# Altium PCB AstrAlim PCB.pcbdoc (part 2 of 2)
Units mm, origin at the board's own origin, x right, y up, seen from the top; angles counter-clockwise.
Board outline 112.02 x 78.49 mm, 4 copper layers (Top Layer, Inner1, Inner2, Bottom Layer); 151 components, 74 nets, 446 pads, 97 vias.
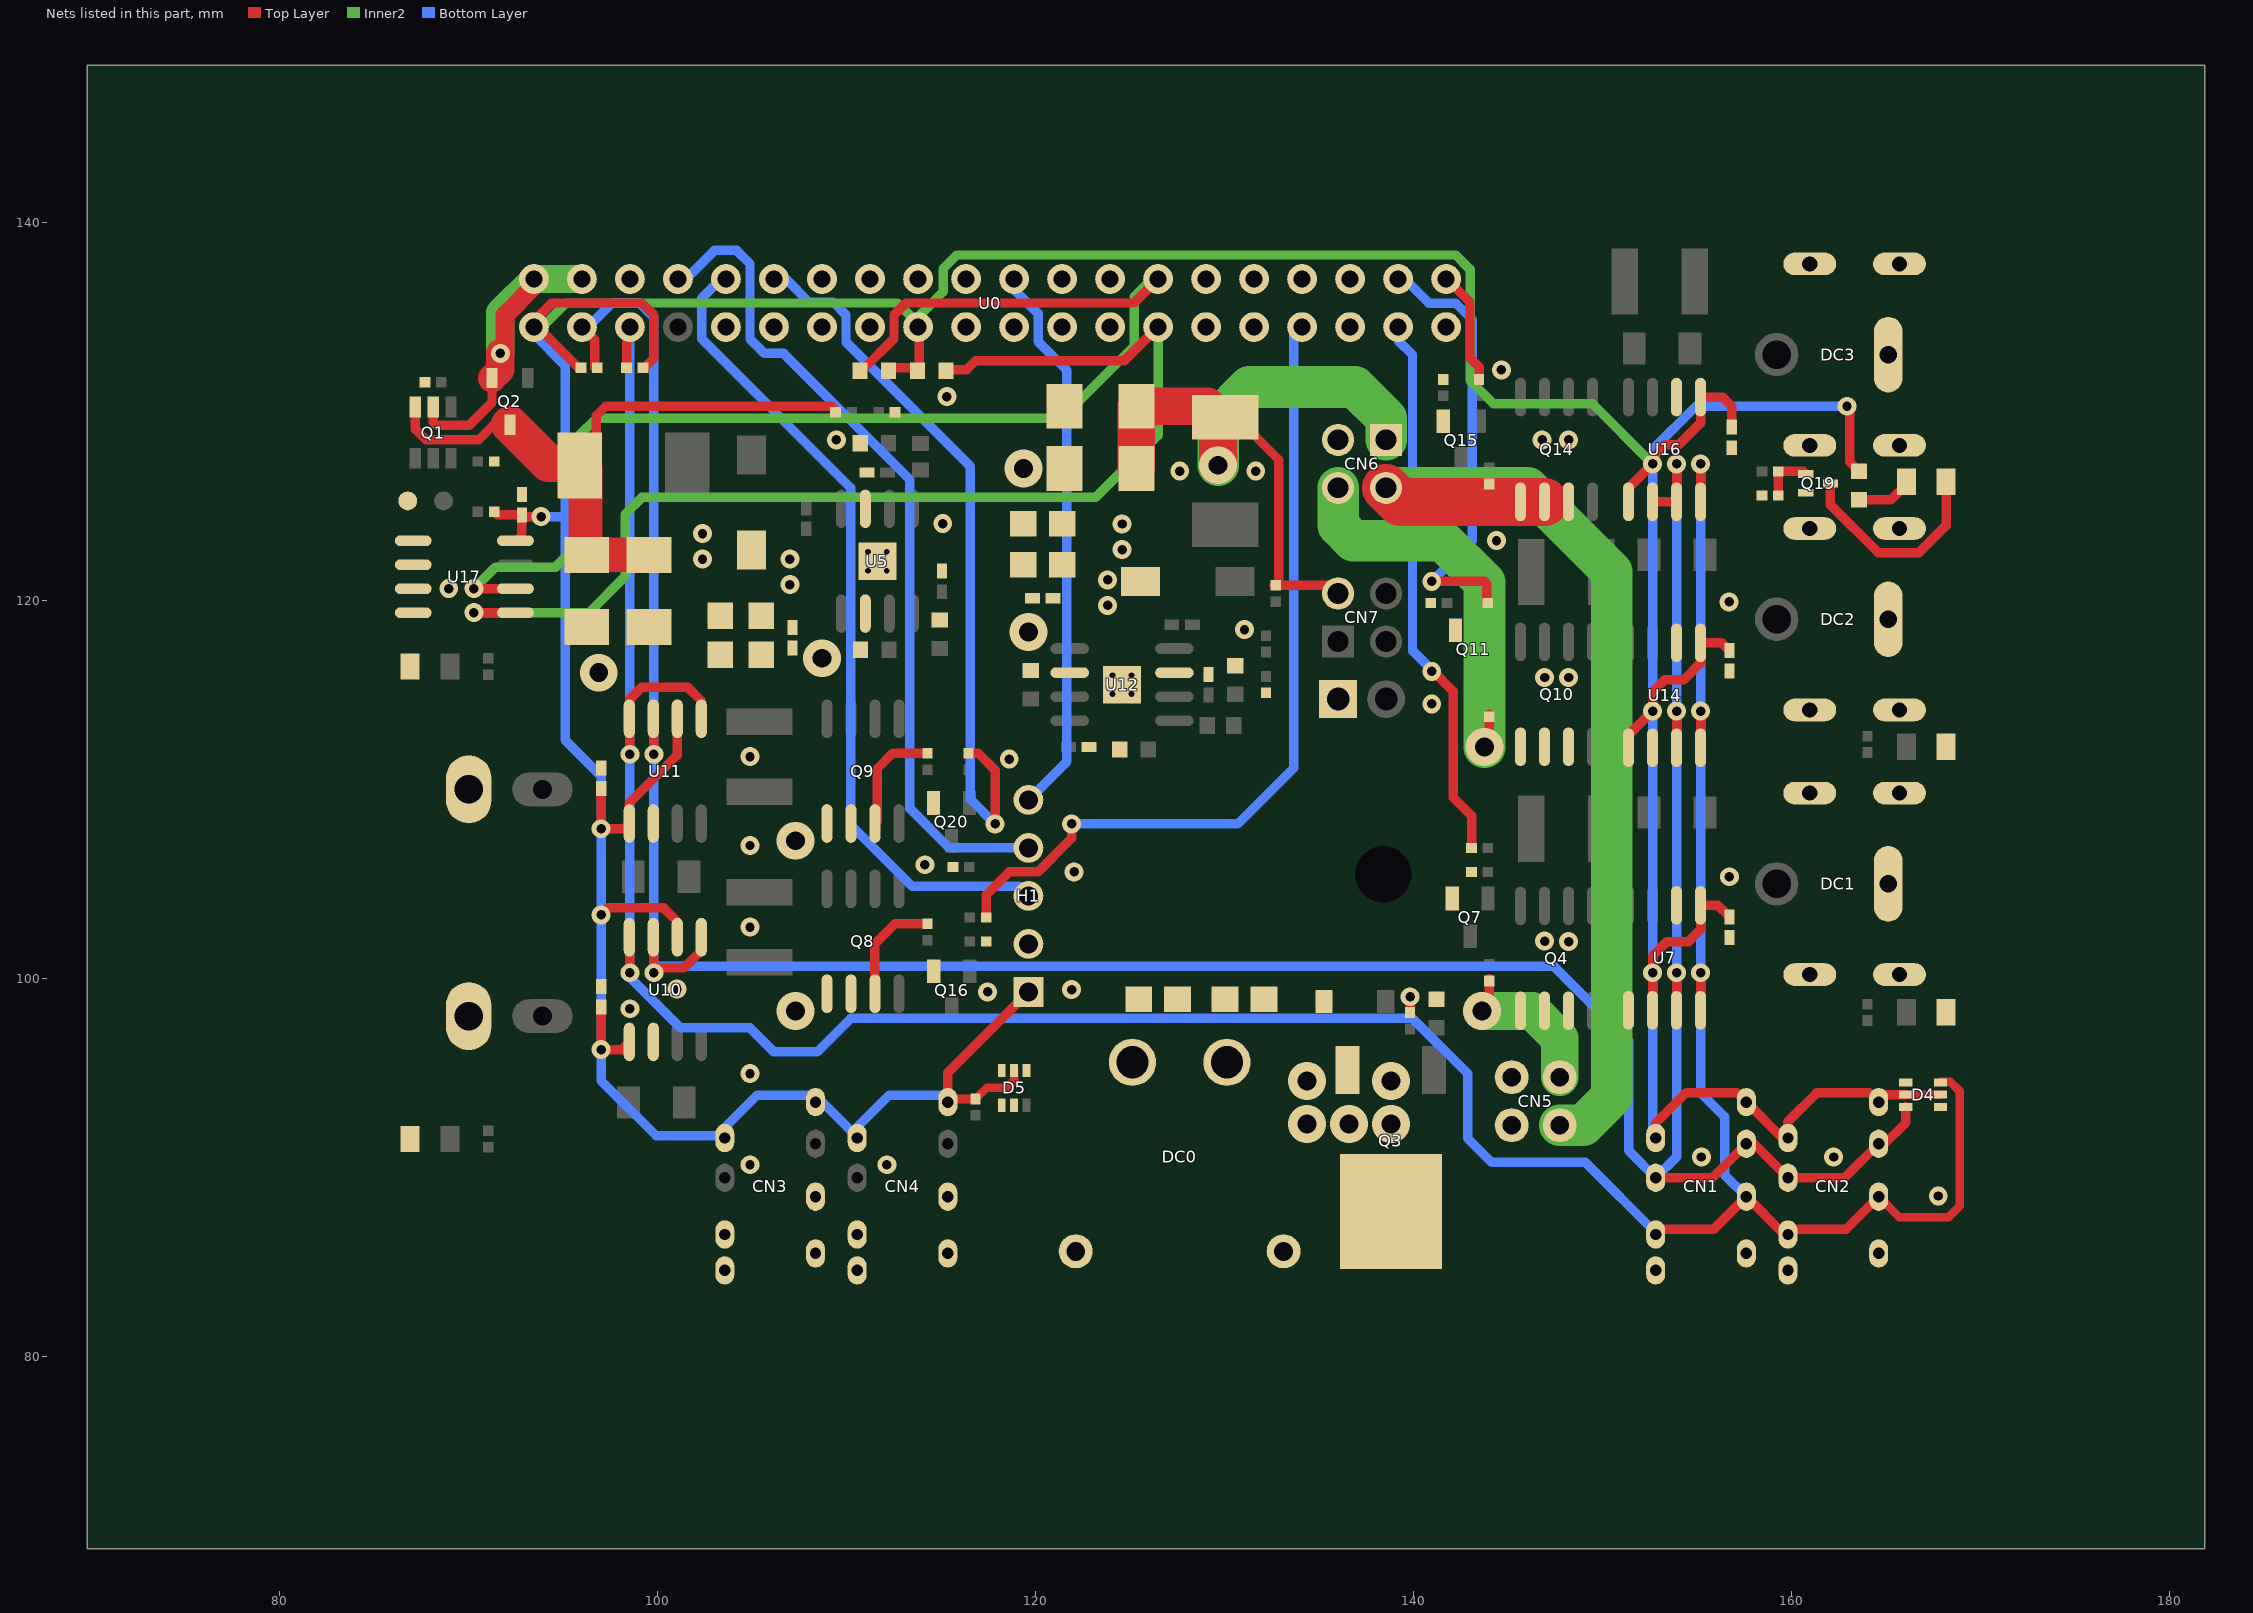
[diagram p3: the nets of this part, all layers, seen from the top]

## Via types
v1: diameter 1, hole 0.5, Top Layer to Bottom Layer, 69 vias
v2: diameter 2, hole 1, Top Layer to Bottom Layer, 14 vias
v3: diameter 0.61, hole 0.305, Top Layer to Bottom Layer, 8 vias
v4: diameter 0.8, hole 0.4, Top Layer to Bottom Layer, 6 vias

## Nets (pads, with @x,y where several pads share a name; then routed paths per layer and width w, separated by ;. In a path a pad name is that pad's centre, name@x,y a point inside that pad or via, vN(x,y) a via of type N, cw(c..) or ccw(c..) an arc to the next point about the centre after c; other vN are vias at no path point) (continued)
$2N49861: Q19.1 R86.1 R87.2 | length 2.8
  Top Layer w0.5: R87.2@159.315,125.586 R86.1@159.315,126.856 160.631,126.856 Q19.1@160.772,126.715
$2N50059: LED13.2 Q19.3 | length 11.1
  Top Layer w0.5: Q19.3@162.072,126.215 162.072,125.08 164.597,122.555 166.756,122.555 168.187,123.986 LED13.2@168.187,126.176
$2N57491: LED13.1 R88.2 | length 2.8
  Top Layer w0.5: R88.2@163.581,125.358 165.268,125.358 LED13.1@166.087,126.176
+3.3V: C16.1 C19.1 C20.1 C30.1 C32.1 C38.2 CN1.4 CN1.8 CN2.4 CN2.8 CN3.4 CN3.8 CN4.4 CN4.8 D4.2 D4.5 D5.5 H1.1 R6.2 R7.2 R19.2 R88.1 R89.2 R90.2 R91.2 U0.1 U0.17 U7.2 U7.5 U10.2 U10.5 U11.2 U11.5 U14.1 U14.5 U16.1 U16.5 U17.8 | length 288.9
  Top Layer w0.45: R19.2@116.845,93.651 117.428,94.234 118.496,94.234 118.877,94.615 D5.5@118.877,95.154 ; D4.5@166.051,93.881 D4.2@167.891,93.881
  Top Layer w0.5: R91.2@91.37,124.714 91.534,124.55 C38.2@92.842,124.55 ; U17.8@92.245,123.19 92.588,123.19 92.842,123.444 C38.2@92.842,124.55 ; v1(93.858,124.46) 92.932,124.46 C38.2@92.842,124.55 ; R6.2@95.838,132.334 93.679,134.493 U0.1@93.477,134.493 93.477,134.813 94.427,135.763 99.184,135.763 99.827,135.12 99.827,132.842 99.319,132.334 R7.2@99.244,132.334 ; C19.1@97.033,98.515 v1(97.033,96.266) 98.119,96.266 U10.5@98.521,96.669 ; v1(97.033,103.394) 97.398,103.759 100.335,103.759 101.061,103.032 U10.2@101.061,102.213 ; C20.1@97.033,110.072 v1(97.033,107.95) 98.246,107.95 U11.5@98.521,108.225 98.521,109.305 101.061,111.845 U11.2@101.061,113.77 ; R90.2@112.579,132.334 113.872,132.334 113.872,134.418 U0.17@113.797,134.493 ; CN4.4@115.418,93.651 CN4.4@115.545,93.651 ; R19.2@116.845,93.651 CN4.4@115.545,93.651 ; H1.1@119.639,99.314 115.377,95.052 CN4.4@115.377,93.483 CN4.4@115.545,93.651 ; U14.1@151.389,112.232 151.389,112.903 v1(152.659,114.173) 152.659,115.189 153.294,115.824 154.31,115.824 155.199,116.713 U14.5@155.199,117.777 156.331,117.777 C30.1@156.723,117.385 ; U16.1@151.389,125.244 151.389,125.984 v1(152.659,127.254) 152.659,127.58 153.349,128.27 154.056,128.27 155.199,129.413 U16.5@155.199,130.788 156.364,130.788 156.85,130.302 C32.1@156.85,129.196 ; U7.2@152.659,98.347 v1(152.659,100.33) 152.659,101.219 153.421,101.981 154.564,101.981 155.199,102.616 U7.5@155.199,103.891 156.12,103.891 C16.1@156.723,103.288 ; CN1.8@152.823,91.583 152.823,92.366 154.437,93.98 157.126,93.98 CN1.4@157.623,93.483 159.523,91.583 CN2.8@159.823,91.583 159.823,92.453 161.353,93.983 164.123,93.983 CN2.4@164.623,93.483 165.021,93.881 D4.5@166.051,93.881 ; v1(162.946,130.302) 163.081,130.167 163.081,127.364 R88.1@163.581,126.864
  Inner2 w0.5: U0.1@93.477,134.493 93.92,134.493 95.19,135.763 112.707,135.763 U0.17@113.797,134.673 ; U0.17@113.797,134.493 U0.17@113.797,134.673 ; v1(152.659,127.254) 149.484,130.429 144.248,130.429 143.007,131.67 143.007,137.541 142.245,138.303 115.85,138.303 115.133,137.586 115.133,136.365 113.797,135.03 U0.17@113.797,134.673
  Bottom Layer w0.5: U0.1@93.477,134.493 93.477,134.116 95.128,132.465 95.128,124.48 ; v1(93.858,124.46) 95.108,124.46 95.128,124.48 ; CN4.4@115.308,93.604 115.059,93.853 112.273,93.853 110.316,91.896 108.359,93.853 105.288,93.853 103.523,92.088 103.523,91.704 99.944,91.704 97.033,94.615 v1(97.033,96.266) v1(97.033,103.394) v1(97.033,107.95) 97.033,110.744 95.128,112.649 95.128,124.48 ; CN1.8@153.077,91.583 152.659,92.001 v1(152.659,100.33) v1(152.659,114.173) v1(152.659,127.254) 152.659,128.004 154.957,130.302 v1(162.946,130.302)
+5V_A: C10.1 C11.1 Q1.6 Q2.3 R14.2 U6.2 | length 34.4
  Top Layer w0.5: Q1.6@87.193,130.255 87.193,129.093 87.762,128.524 90.556,128.524 91.353,129.321 Q2.3@92.207,129.321 ; U6.2@95.89,127.285 96.779,128.174 96.779,129.802 97.279,130.302 109.237,130.302 109.427,130.112 R14.2@109.427,129.984
  Top Layer w1.8: U6.2@95.89,127.285 96.2,126.975 96.2,122.473 96.229,122.444 C11.1@98.482,122.444
  Top Layer w2: Q2.3@92.207,129.321 94.243,127.285 U6.2@95.89,127.285
+5V_PI: Q1.5 Q2.2 U0.2 U0.4 | length 19.2
  Top Layer w0.5: Q1.5@88.143,130.255 88.143,129.451 88.308,129.286 90.048,129.286 91.257,130.495 Q2.2@91.257,131.791
  Top Layer w1: v1(91.699,133.096) 91.953,133.35 91.953,135.128 93.477,136.652 U0.2@93.477,137.033
  Top Layer w1.5: Q2.2@91.257,131.791 91.699,132.233 v1(91.699,133.096)
  Inner2 w1.5: v1(91.699,133.096) 91.699,135.255 U0.2@93.477,137.033 U0.4@96.017,137.033
+9V: C26.1 C27.1 CN6.1 CN7.2 R67.2 U13.2 | length 38.7
  Top Layer w0.5: U13.2@129.672,129.723 130.632,129.723 132.887,127.468 132.887,121.071 132.645,120.829 135.589,120.829 CN7.2@136.022,120.396
  Top Layer w2: C27.1@125.348,127 C26.1@125.348,130.302 129.093,130.302 129.672,129.723 v2(129.672,127.182)
  Inner2 w2.2: v2(129.672,127.182) 129.672,129.667 131.323,131.318 136.911,131.318 138.562,129.667 CN6.1@138.562,128.524
+12V: C5.2 C6.2 C7.2 C21.2 C22.2 C23.2 C34.2 C35.2 CN5.2 CN6.4 DC0.2 Q4.1 Q4.2 Q4.3 Q8.1 Q8.2 Q8.3 Q9.1 Q9.2 Q9.3 Q10.1 Q10.2 Q10.3 R10.2 R17.1 R22.2 R27.2 R30.2 R32.2 R42.2 U5.2 U12.2 | length 42.8
  Top Layer w0.5: Q8.3@111.518,99.219 111.511,99.227 111.511,101.854 112.579,102.922 R27.2@114.305,102.922 ; Q9.3@111.518,108.225 111.638,108.345 111.638,111.125 112.452,111.939 R30.2@114.305,111.939 ; R17.1@139.832,98.223 v1(139.832,99.06) ; v2(143.642,98.298) 144.023,98.679 R22.2@144.023,100.024 ; v2(143.769,112.268) 144.023,112.522 R42.2@144.023,113.994
  Inner2 w2: v2(143.642,98.298) 146.309,98.298 147.747,96.86 CN5.2@147.747,94.803
  Inner2 w2.2: CN6.4@136.022,125.984 136.022,123.993 136.825,123.19 141.569,123.19 143.769,120.99 v2(143.769,112.268)
  other v2: 107.32,98.298 107.32,107.315 108.717,116.967 119.639,118.364
GND: AV0.1 AV1.1 C5.1 C6.1 C7.1 C8.1 C10.2 C11.2 C13.1 C16.2 C19.2 C20.2 C21.1 C22.1 C23.1 C24.1 C26.2 C27.2 C29.1 C30.2 C32.2 C34.1 C35.1 C38.1 CN1.1 CN1.5 CN2.1 CN2.5 CN3.1 CN3.5 CN4.1 CN4.5 CN5.1 CN5.3 CN8.1 D1.1 D2.2 D3.1 D4.1 D4.4 D5.4 DC1.2 DC1.3 DC2.2 DC2.3 DC3.2 DC3.3 GN0.1 H1.2 LED1.2 LED2.2 LED4.2 LED5.2 pad.41 Q3.3 Q7.2 Q11.2 Q15.2 Q16.2 Q19.2 Q20.2 R11.1 R12.2 R13.1 R16.1 R18.1 R20.1 R33.1 R34.2 R39.1 R40.1 R48.1 R54.1 R56.1 R59.1 R87.1 U0.6 U0.9 U0.14 U0.20 U0.25 U0.30 U0.34 U0.39 U5.7 U5.9 U7.1 U7.6 U10.6 U11.6 U12.7 U12.9 U14.2 U14.6 U16.6 U17.3 U17.4
  other v1: 167.772,88.519 104.907,90.17 112.146,90.17 155.242,90.581 162.242,90.581 104.907,94.996 98.557,98.425 117.48,99.314 121.925,99.441 101.044,99.462 148.214,101.981 146.944,102 104.907,102.743 156.723,105.41 122.052,105.664 114.164,106.045 104.907,107.061 118.623,111.633 104.907,111.76 140.975,114.554 146.944,115.951 148.214,115.951 131.069,118.481 123.83,119.761 156.713,119.955 88.969,120.65 107.021,120.863 123.83,121.113 102.396,122.215 107.021,122.215 124.592,122.719 144.404,123.19 102.396,123.565 124.592,124.071 115.104,124.095 127.643,126.873 131.664,126.873 109.479,128.524 146.817,128.524 148.214,128.524 115.321,130.81 144.658,132.222
  other v2: 134.371,92.329 136.593,92.329 138.816,92.329 134.371,94.605 138.816,94.605 96.906,116.205 119.385,127
GND_IN: DC0.1 Q3.2
GPIO13_PWM1: R53.1 U0.33 | length 44.2
  Top Layer w0.5: R53.1@117.405,103.251 117.405,104.446 118.623,105.664 120.147,105.664 121.925,107.442 v1(121.925,108.204)
  Bottom Layer w0.5: v1(121.925,108.204) 130.715,108.204 133.672,111.161 133.672,133.99 U0.33@134.128,134.447
GPIO18_PWM0: R55.1 U0.12 | length 39.4
  Top Layer w0.5: R55.1@116.464,111.939 116.984,111.939 117.873,111.05 v1(117.873,108.204)
  Bottom Layer w0.5: U0.12@106.177,137.033 106.804,137.033 108.035,135.802 109.313,135.802 109.987,135.128 109.987,133.698 116.566,127.119 116.566,109.511 v1(117.873,108.204)
GPIO20: R41.1 U0.38 | length 23.5
  Top Layer w0.5: v1(140.975,121.031) 143.769,121.031 143.896,120.904 143.896,119.94 R41.1@143.948,119.888
  Bottom Layer w0.5: U0.38@139.22,136.951 139.63,136.951 140.829,135.752 142.245,135.752 143.117,134.881 143.117,123.173 v1(140.975,121.031)
GPIO21: R49.1 U0.40 | length 6
  Top Layer w0.5: U0.40@141.794,137.013 143,135.807 143,132.855 143.495,132.361 R49.1@143.495,131.727
GPIO26: R21.1 U0.37 | length 29.2
  Top Layer w0.5: v1@141.064,116.269 142.118,115.215 142.118,109.601 143.092,108.627 143.082,108.617 R21.1@143.082,106.934
  Bottom Layer w0.5: U0.37@139.197,134.493 139.197,133.786 139.959,133.024 139.959,117.374 v1@141.064,116.269
  other v1: 140.975,116.269
ID_SC: R90.1 U0.28 U17.6 | length 68.3
  Top Layer w0.5: v1(90.302,120.65) U17.6@92.245,120.65 ; R90.1@110.732,132.285 110.922,132.285 112.527,133.89 112.527,135.128 113.162,135.763 125.227,135.763 U0.28@126.497,137.033
  Inner2 w0.5: v1(90.302,120.65) 91.445,121.793 94.62,121.793 95.89,123.063 95.89,128.778 96.779,129.667 121.417,129.667 125.227,133.477 125.227,136.095 126.165,137.033 U0.28@126.497,137.033
ID_SD: R89.1 U0.27 U17.5 | length 61.8
  Top Layer w0.5: v1(90.302,119.38) U17.5@92.245,119.38 ; R89.1@115.331,132.231 116.369,132.231 116.852,132.715 ; 116.856,132.719 116.852,132.715 ; U0.27@126.497,134.493 124.719,132.715 116.852,132.715
  Inner2 w0.5: v1(90.302,119.38) 96.398,119.38 98.303,121.285 98.303,124.587 99.192,125.476 123.195,125.476 126.497,128.778 U0.27@126.497,134.493
PPS: H1.5 U0.22 | length 29.6
  Bottom Layer w0.5: U0.22@118.877,137.033 118.877,136.479 120.147,135.209 120.147,133.731 121.671,132.207 121.671,111.506 H1.5@119.639,109.474
RXD: H1.3 U0.10 | length 43.8
  Bottom Layer w0.5: U0.10@103.637,137.033 103.375,137.033 102.367,136.025 102.367,133.858 110.241,125.984 110.241,108.142 113.489,104.894 119.139,104.894 H1.3@119.639,104.394
SCL: CN1.2 CN1.6 CN2.2 CN2.6 D4.3 R7.1 U0.5 U7.4 U10.4 U11.1 U11.4 U14.4 U16.4 | length 182.6
  Top Layer w0.45: CN2.2@164.623,88.483 165.723,87.383 168.304,87.383 168.915,87.994 168.915,94.058 168.415,94.558 D4.3@167.917,94.558
  Top Layer w0.5: R7.1@98.378,132.334 98.378,134.314 U0.5@98.557,134.493 ; U10.4@98.521,102.213 98.557,102.178 v1(98.557,100.33) ; U11.4@98.521,113.77 U11.4@98.557,113.735 ; v1(98.557,111.887) U11.4@98.557,113.735 ; U11.1@102.331,113.77 102.331,114.716 101.605,115.443 99.192,115.443 98.557,114.808 U11.4@98.557,113.735 ; CN1.6@152.823,86.483 153.107,86.767 155.907,86.767 CN1.2@157.623,88.483 159.623,86.483 CN2.6@159.823,86.483 160.107,86.767 162.907,86.767 CN2.2@164.623,88.483 ; U7.4@155.199,98.347 v1(155.199,100.33) ; U14.4@155.199,112.232 v1(155.199,114.173) ; U16.4@155.199,125.244 v1(155.199,127.254)
  Bottom Layer w0.5: U0.5@98.557,134.493 v1(98.557,111.887) v1(98.557,100.33) 98.557,100.076 101.224,97.409 104.907,97.409 106.177,96.139 108.463,96.139 110.241,97.917 139.959,97.917 142.88,94.996 142.88,91.567 144.15,90.297 149.103,90.297 CN1.6@152.854,86.546 ; CN1.6@152.663,86.483 CN1.6@152.823,86.483 ; v1(155.199,127.254) v1(155.199,114.173) v1(155.199,100.33) 155.199,93.98 156.469,92.71 156.469,89.637 CN1.2@157.623,88.483
SDA: CN1.3 CN1.7 CN2.3 CN2.7 D4.6 R6.1 U0.3 U7.3 U10.1 U10.3 U11.3 U14.3 U16.2 U16.3 | length 172.4
  Top Layer w0.5: U0.3@96.017,134.493 96.704,133.806 R6.1@96.704,132.334 ; U10.3@99.791,102.213 99.827,102.178 v1(99.827,100.33) 100.081,100.584 101.409,100.584 102.331,101.506 U10.1@102.331,102.213 ; U11.3@99.791,113.77 99.827,113.735 v1(99.827,111.887) ; U16.2@152.659,125.244 U16.3@153.929,125.244 v1(153.929,127.254) ; CN1.7@152.823,89.483 155.823,89.483 CN1.3@157.623,91.283 ; U7.3@153.929,98.347 v1(153.929,100.33) ; U14.3@153.929,112.232 v1(153.929,114.173) ; CN1.3@157.877,91.283 158.023,91.283 CN2.7@159.823,89.483 162.823,89.483 CN2.3@164.623,91.283 164.948,91.283 166.051,92.386 D4.6@166.051,93.231
  Bottom Layer w0.5: U0.3@96.017,134.493 96.329,134.493 97.599,135.763 99.065,135.763 99.827,135.001 v1(99.827,111.887) v1(99.827,100.33) 100.161,100.664 147.45,100.664 151.389,96.726 151.389,90.917 152.823,89.483 153.929,90.589 v1(153.929,100.33) v1(153.929,114.173) v1(153.929,127.254)
TXD: H1.4 U0.8 | length 44.8
  Bottom Layer w0.5: U0.8@101.097,137.033 101.515,137.033 103.028,138.546 104.199,138.546 104.907,137.839 104.907,133.858 105.669,133.096 106.685,133.096 113.367,126.414 113.367,109.015 115.448,106.934 H1.4@119.639,106.934
VS: CN5.4 CN6.2 Q14.1 Q14.2 Q14.3 R50.2 | length 53.6
  Top Layer w2.54: CN6.2@138.562,125.984 139.324,125.222 146.922,125.222 Q14.2@146.944,125.244
  Inner2 w2.2: CN6.2@138.562,125.984 146.055,125.984 150.5,121.539 150.5,93.779 148.984,92.263 CN5.4@147.747,92.263
"": CN3.2 CN3.6 CN4.2 CN4.6 CN6.3 D5.1 D5.2 D5.6 DC0.3 DC0.4 U0.11 U0.13 U0.15 U0.16 U0.18 U0.19 U0.21 U0.23 U0.24 U0.26 U0.29 U0.31 U0.32 U0.35 U0.36 U17.1 U17.2
  other v3: 124.092,115.07 125.092,115.07 124.092,116.07 125.092,116.07 111.146,121.602 112.146,121.602 111.146,122.602 112.146,122.602

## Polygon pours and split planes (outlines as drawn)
GND on Top Layer (solid, remove dead copper, pour order 0): 82.428,78.74 173.614,78.74 173.614,141.986 82.428,141.986
GND on Top Layer (solid, remove dead copper, pour order 1): 82.428,76.454 173.614,76.454 173.614,139.7 82.428,139.7
GND on Bottom Layer (solid, remove dead copper, pour order 2): 82.428,77.47 173.614,77.47 173.614,140.716 82.428,140.716
GND on Inner1 (solid, remove dead copper, pour order 3): 82.428,76.835 173.614,76.835 173.614,140.081 82.428,140.081
GND on Inner2 (solid, remove dead copper, pour order 4): 82.682,76.2 173.868,76.2 173.868,139.446 82.682,139.446

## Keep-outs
Top Layer:
  region net "": 101.15,104.14 ccw(c100.97,104.14) 100.79,104.14 ccw(c100.97,104.14)
  region net "": 155.692,134.662 155.86,134.662 155.86,134.938 155.692,134.938
Bottom Layer:
  region net "": 152.148,96.961 ccw(c152.005,96.961) 151.862,96.961 ccw(c152.005,96.961)
  region net "": 100.335,108.623 100.721,108.623 100.721,111.125 100.335,111.125
  region net "": 97.668,111.76 97.258,111.35 97.258,111.347 97.607,110.998 97.9,110.998 97.9,111.528
  region net "": 97.532,99.286 97.795,99.695 98.176,99.695 97.922,99.441
  region net "": 97.541,99.441 97.795,99.695 98.176,99.695 97.922,99.441

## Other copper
Top Layer:
  region net +12V: 108.209,115.951 107.828,116.332 103.897,116.332 103.885,116.332 102.621,116.324 102.621,117.983 110.152,117.983 110.622,118.453 110.622,120.329 110.874,120.581 111.126,120.581 111.419,120.288 111.419,116.621 110.749,115.951
  region net +12V: 119.24,115.842 118.691,116.391 118.626,116.489 118.613,116.52 118.59,116.635 118.59,124.633 118.678,124.845 118.702,124.869 118.914,124.957 119.95,124.957 120.162,124.869 120.245,124.786 120.333,124.574 120.333,119.845 120.546,118.338 120.441,117.278 120.549,116.978 120.936,116.674 121.001,116.636 121.056,116.611 121.176,116.586 122.544,116.586 122.659,116.563 122.69,116.55 122.788,116.485 122.84,116.433 122.905,116.335 122.918,116.304 122.941,116.189 122.941,116.138 122.918,116.023 122.905,115.992 122.84,115.894 122.788,115.842 122.69,115.777 122.659,115.764 122.544,115.741 119.483,115.741 119.369,115.764 119.337,115.777
  region net +12V: 143.769,111.147 cw(c143.769,112.29) 142.626,112.29 cw(c143.769,112.29) 143.769,113.433 148.522,113.433 148.722,113.233 148.722,111.347 148.522,111.147
  region net +12V: 143.642,97.155 cw(c143.642,98.298) 142.499,98.298 cw(c143.642,98.298) 143.642,99.441 148.395,99.441 148.595,99.241 148.595,97.355 148.395,97.155
  region net +12V: 106.729,108.103 108.396,108.922 108.407,108.929 109.009,109.33 109.065,109.347 111.792,109.347 111.892,109.247 111.892,107.157 111.792,107.057 108.5,107.057 108.43,107.028 108.026,106.624 107.884,106.624 106.702,107.806 106.673,107.877 106.673,108.013
  region net +12V: 106.729,99.095 108.396,99.914 108.407,99.921 109.009,100.323 109.065,100.339 111.792,100.339 111.892,100.239 111.892,98.149 111.792,98.049 108.5,98.049 108.43,98.02 108.026,97.616 107.884,97.616 106.702,98.798 106.673,98.869 106.673,99.005
  region net $2N3430: 145.493,116.84 149.538,116.84 149.738,117.04 149.738,118.672 149.538,118.872 145.493,118.872 145.293,118.672 145.293,117.04
  region net VS: 146.89,123.952 148.432,123.952 148.632,124.152 148.632,126.295 148.432,126.495 146.89,126.495 146.69,126.295 146.69,124.152
  region net $2N538: 145.239,102.87 149.792,102.87 149.992,103.07 149.992,104.702 149.792,104.902 145.239,104.902 145.039,104.702 145.039,103.07
  region net $2N1618: 103.837,112.649 112.835,112.649 113.035,112.849 113.035,114.608 112.835,114.808 103.837,114.808 103.637,114.608 103.637,112.849
  region net $2N1605: 103.935,103.725 103.793,103.866 103.764,103.937 103.764,105.31 103.864,105.41 107.805,105.41 107.849,105.42 108.733,105.845 108.777,105.855 112.921,105.855 112.991,105.825 113.133,105.684 113.162,105.613 113.162,103.937 113.133,103.866 112.991,103.725 112.921,103.695 104.005,103.695
  region net $2N4466: 145.493,129.794 145.293,129.994 145.293,131.626 145.493,131.826 148.314,131.826 148.522,131.826 149.765,131.826 149.865,131.726 149.865,129.894 149.765,129.794 148.522,129.794 148.314,129.794
  region net $1N14596: 126.243,117.294 126.243,117.783 126.443,117.983 127.694,117.983 127.894,118.183 127.894,119.424 127.953,119.566 129.359,120.972 129.418,121.114 129.418,123.498 129.618,123.698 131.123,123.698 131.323,123.498 131.323,120.098 131.264,119.956 128.461,117.153 128.319,117.094 126.443,117.094
  region net $1N4920: 110.114,124.025 109.914,123.825 109.308,123.825 109.166,123.884 108.518,124.532 108.377,124.59 107.586,124.59 107.386,124.79 107.386,124.819 105.967,126.238 102.367,126.238 102.367,128.778 105.009,128.778 106.025,128.778 107.364,128.778 107.506,128.719 110.055,126.17 110.114,126.028
  region net +5V_A: 93.477,126.619 95.578,124.518 96.598,124.518 96.598,126.578 96.2,126.975 93.833,126.975
  region net +5V_A: 94.747,128.905 93.858,128.905 94.792,127.97 95.128,127.97 95.128,128.524
  region net $1N59627: 126.606,110.744 126.606,111.033 126.306,111.333 125.628,111.333 125.328,111.033 125.328,110.744 125.628,110.444 126.306,110.444
  region net $2N3428: 153.06,123.268 153.05,123.268 153.05,123.279
  region net $2N3428: 153.05,123.268 150.24,123.268 149.82,122.847 149.82,120.638 150.598,119.859 152.355,121.616 153.05,121.616
  region net $2N40244: 154.828,123.436 157.668,123.436 157.763,123.342 157.763,121.522 157.563,121.322 154.828,121.322 154.828,123.415 154.838,123.426
  region net +12V: 126.811,99.659 130.7,99.659 130.746,99.613 130.746,98.379 130.834,98.167 132.02,96.981 132.108,96.769 132.108,95.047 132.02,94.835 130.834,93.649 130.622,93.561 129.571,93.561 129.359,93.649 127.901,95.108 127.813,95.32 127.813,95.805 127.008,97.747 126.765,97.99 126.765,99.613
  region net GND_IN: 141.61,90.505 141.61,84.88 141.31,84.58 135.005,84.58 134.793,84.668 134.713,84.748 134.625,84.96 134.625,86.236 134.537,86.448 133.951,87.034 133.739,87.122 129.036,87.122 128.824,87.21 123.655,92.378 123.568,92.59 123.568,95.591 123.57,95.591 cw(c125.14,95.591) 125.14,97.161 cw(c125.14,95.591) 126.71,95.591 126.71,94.526 126.798,94.314 128.558,92.554 128.77,92.466 131.888,92.466 132.1,92.378 133.585,90.893 133.797,90.805 141.31,90.805
Inner2:
  region net +12V: 129.088,93.654 128.735,93.8 127.66,94.874 127.514,95.228 127.514,95.558 127.367,95.911 125.535,97.744 124.828,97.744 122.535,95.451 122.181,95.304 108.42,95.304 108.066,95.451 105.88,97.637 105.733,97.991 105.733,116.502 105.88,116.855 107.384,118.36 107.738,118.506 108.767,118.506 109.121,118.653 110.278,119.81 110.4,119.81 110.4,119.82 119.716,119.82 120.07,119.674 121.474,118.269 121.62,117.916 121.62,115.831 121.767,115.478 123.69,113.555 124.043,113.408 144.421,113.408 144.774,113.262 145.236,112.8 145.382,112.447 145.382,98.198 145.236,97.845 144.067,96.676 143.714,96.53 134.321,96.53 133.968,96.383 131.385,93.8 131.031,93.654
Bottom Layer:
  region net +3.3V: 95.435,123.944 95.435,124.832 95.235,125.032 94.767,125.032 94.567,124.832 94.567,123.944 94.767,123.744 95.235,123.744

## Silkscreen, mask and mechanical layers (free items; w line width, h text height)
Top Silkscreen Layer:
  circle w3 net "": c146.512,86.766 r1.5
  circle w3 net "": c88.6,86.766 r1.5
  circle w3 net "": c88.6,135.788 r1.5
  circle w3 net "": c146.512,135.788 r1.5
  circle w3 net "": c138.409,105.534 r1.5
  region net "": 118.977,87.033 ccw(c118.477,87.033) 117.977,87.033 ccw(c118.477,87.033)
  region net "": 90.686,104.033 ccw(c90.186,104.033) 89.686,104.033 ccw(c90.186,104.033)
  region net "": 158.977,98.033 ccw(c158.477,98.033) 157.977,98.033 ccw(c158.477,98.033)
  lines w0.3 net "": 94.366,116.697 ccw(c95.366,116.697) 95.366,115.697 114.88,115.697 ccw(c114.88,116.697) 115.88,116.697 115.88,130.279 ccw(c114.88,130.279) 114.88,131.279 95.366,131.279 ccw(c95.366,130.279) 94.366,130.279 94.366,116.697 ; 117.479,112.125 ccw(c118.479,112.125) 118.479,111.125 132.863,111.125 ccw(c132.863,112.125) 133.863,112.125 133.863,131.715 ccw(c132.863,131.715) 132.863,132.715 118.479,132.715 ccw(c118.479,131.715) 117.479,131.715 117.479,112.125
  text "[mA]" at 155.837,130.879 h0.52
  text "Vs" at 136.444,130.451 h0.97
  text "Vt" at 118.188,130.238 h1.3
  text "RPi" at 105.487,130.143 h0.65
  text "5V" at 102.694,129.476 h1.3
  text "9V/5V" at 117.644,129.337 h0.52
  text "OUT3 /  [Vs]" at 157.457,125.195 h0.51 r90
  text "Vt" at 136.506,122.261 h0.97
  text "PWM0 /  [12V]" at 91.962,117.745 h0.51 r270
  text "[mA]" at 156.945,113.42 h0.52 r90
  text "Disable Vt" at 134.497,112.617 h0.65
  text "[mA]" at 97.255,112.163 h0.52 r90
  text "OUT2 /  [12V]" at 162.918,111.051 h0.51 r90
  text "GPS /  PPS" at 121.182,108.867 h0.51
  text "GPS /  RXD" at 121.182,106.359 h0.51
  text "v1.0" at 135.038,104.455 h0.65 r90
  text "GPS /  TXD" at 121.182,103.851 h0.51
  text "GPS /  GND" at 121.182,101.343 h0.51
  text "[mA]" at 97.236,100.517 h0.52 r90
  text "[mA]" at 156.945,99.371 h0.52 r90
  text "OUT1 /  [12V]" at 162.918,97.081 h0.51 r90
  text "GPS /  VCC" at 118.896,96.548 h0.51
  text "GND" at 143.595,93.938 h0.65 r90
  text "https://oshwlab.com/ /  pololamag/nafa-astralim" at 93.632,93.612 h0.51 r270
  text "[12V]" at 150.072,93.5 h0.65 r90
  text "PWM1 /  [12V]" at 92.043,92.721 h0.51 r270
  text "12V" at 132.917,91.87 h0.91 r90
  text "GND" at 123.265,91.743 h0.91 r90
  text "GND" at 143.602,91.319 h0.65 r90
  text "[Vs]" at 150.079,91.163 h0.65 r90
  text "I2C OUT" at 166.931,84.582 h0.97 r90
  text "1-Wire" at 117.528,83.99 h0.97 r90
  text "DC 12V IN" at 120.322,83.861 h0.97 r90
Bottom Silkscreen Layer:
  lines w0.15 net "": 82.532,93.159 ccw(c84.032,93.159) 84.032,91.659 94.794,91.659 ccw(c94.794,93.159) 96.294,93.159 96.294,101.659 ccw(c94.794,101.659) 94.794,103.159 84.032,103.159 ccw(c84.032,101.659) 82.532,101.659 82.532,93.159 ; 82.532,105.097 ccw(c84.032,105.097) 84.032,103.597 94.794,103.597 ccw(c94.794,105.097) 96.294,105.097 96.294,113.597 ccw(c94.794,113.597) 94.794,115.097 84.032,115.097 ccw(c84.032,113.597) 82.532,113.597 82.532,105.097 ; 102.24,81.256 ccw(c103.74,81.256) 103.74,79.756 118.901,79.756 ccw(c118.901,81.256) 120.401,81.256 120.401,92.988 ccw(c118.901,92.988) 118.901,94.488 103.74,94.488 ccw(c103.74,92.988) 102.24,92.988 102.24,81.256 ; 120.718,81.129 ccw(c122.218,81.129) 122.218,79.629 133.76,79.629 ccw(c133.76,81.129) 135.26,81.129 135.26,95.909 ccw(c133.76,95.909) 133.76,97.409 122.218,97.409 ccw(c122.218,95.909) 120.718,95.909 120.718,81.129 ; 151.255,81.256 ccw(c152.755,81.256) 152.755,79.756 170.59,79.756 ccw(c170.59,81.256) 172.09,81.256 172.09,93.115 ccw(c170.59,93.115) 170.59,94.615 152.755,94.615 ccw(c152.755,93.115) 151.255,93.115 151.255,81.256 ; 157.262,100.741 ccw(c158.762,100.741) 158.762,99.241 170.762,99.241 ccw(c170.762,100.741) 172.262,100.741 172.262,109.241 ccw(c170.762,109.241) 170.762,110.741 158.762,110.741 ccw(c158.762,109.241) 157.262,109.241 157.262,100.741 ; 157.262,114.741 ccw(c158.762,114.741) 158.762,113.241 170.762,113.241 ccw(c170.762,114.741) 172.262,114.741 172.262,123.241 ccw(c170.762,123.241) 170.762,124.741 158.762,124.741 ccw(c158.762,123.241) 157.262,123.241 157.262,114.741 ; 157.262,128.741 ccw(c158.762,128.741) 158.762,127.241 170.762,127.241 ccw(c170.762,128.741) 172.262,128.741 172.262,137.241 ccw(c170.762,137.241) 170.762,138.741 158.762,138.741 ccw(c158.762,137.241) 157.262,137.241 157.262,128.741
  text "GND" at 169.53,135.612 h0.65
  text "Vs" at 159.236,135.477 h0.65
  text "DC /  OUT" at 163.744,132.066 h1.09
  text "GND" at 169.473,121.544 h0.65
  text "12V" at 159.215,121.488 h0.65
  text "https://oshwlab.com/pololamag/nafa-astralim" at 151.821,118.558 h0.52 r90
  text "DC /  OUT" at 163.776,117.866 h1.09
  text "GND" at 93.295,107.791 h0.65
  text "GND" at 169.53,107.545 h0.65
  text "12V" at 159.272,107.488 h0.65
  text "PWM /  +12V" at 95.161,103.981 h0.72
  text "DC /  OUT" at 163.745,103.866 h1.09
  text "v1.0" at 130.237,101.669 h0.65
  text "GND" at 93.295,95.861 h0.65
  text "3.3V" at 120.051,92.344 h0.65
  text "3.3V" at 169.47,92.275 h0.65
  text "DC IN" at 129.757,92.154 h0.97
  text "PWM /  +12V" at 95.161,92.051 h0.72
  text "SCL" at 169.087,91.339 h0.65
  text "1-W" at 119.711,91.281 h0.65
  text "SDA" at 169.168,90.403 h0.65
  text "GND" at 119.722,89.664 h0.65
  text "GND" at 169.141,89.468 h0.65
  text "GND" at 126.823,86.582 h0.65
  text "12V" at 130.506,86.582 h0.65
  text "JLCJLCJLCJLC" at 98.372,84.296 h0.65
